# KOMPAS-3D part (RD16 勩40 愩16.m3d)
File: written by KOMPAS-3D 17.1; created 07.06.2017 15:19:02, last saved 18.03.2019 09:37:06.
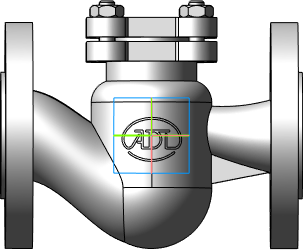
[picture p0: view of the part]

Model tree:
1. Операция без истории:3  (labels: Сталь 20  ГОСТ 1050-88)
